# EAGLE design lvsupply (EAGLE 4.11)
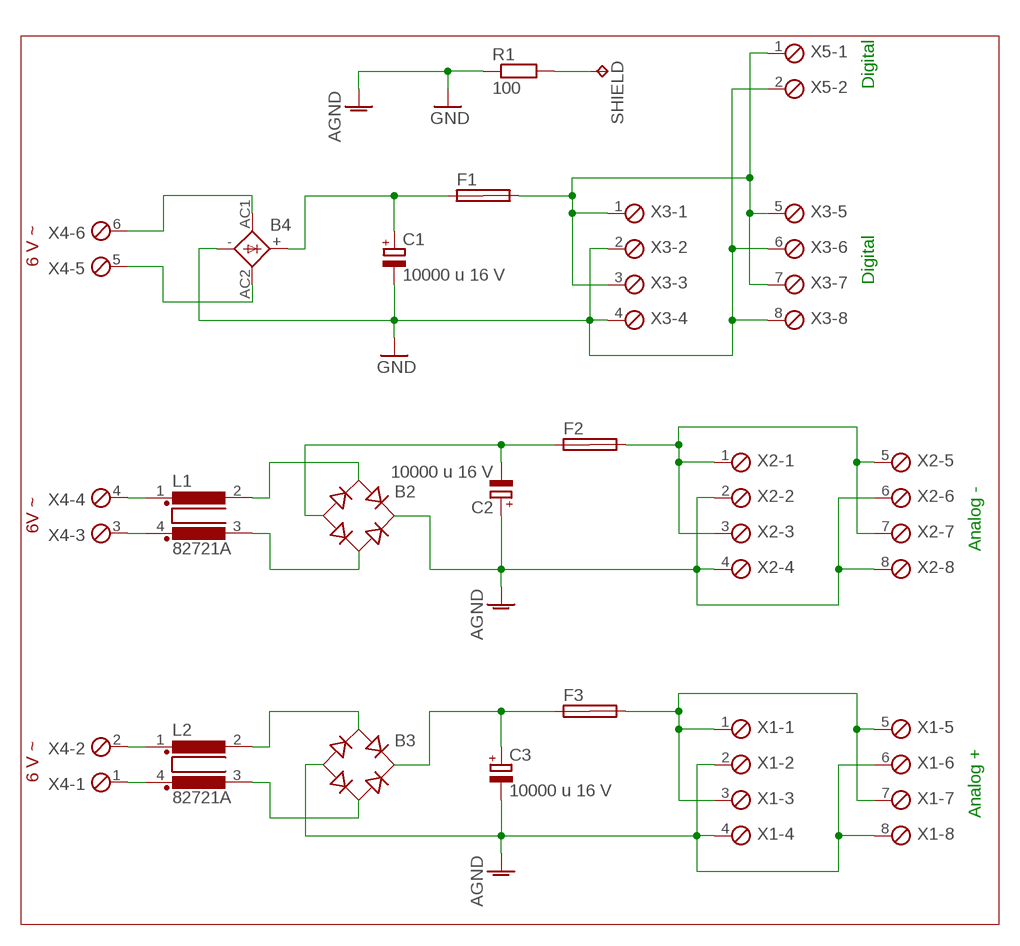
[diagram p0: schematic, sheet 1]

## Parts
B2  RB1A  [RB1A]
B3  RB1A  [RB1A]
B4  SKBB  [SKBB]
C1  10000 u 16 V  CPOL-EUE10-25  [EB25D]
C2  10000 u 16 V  CPOL-EUE10-25  [EB25D]
C3  10000 u 16 V  CPOL-EUE10-25  [EB25D]
F1  SHK20Q  [SHK20Q]
F2  SHK20Q  [SHK20Q]
F3  SHK20Q  [SHK20Q]
L1  82721A  [82721A]
L2  82721A  [82721A]
R1  100  R-EU_0309/12  [0309/12]
SHIELD  TPPAD1-20Y  [P1-20Y]
X1  MPT8  [8POL254]
X2  MPT8  [8POL254]
X3  MPT8  [8POL254]
X4  MPT6  [6POL254]
X5  MPT2  [2POL254]

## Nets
GND: B2.+ B3.- B4.- C1.- C2.+ C3.- R1.1 X1.2 X1.4 X1.6 X1.8 X2.2 X2.4 X2.6 X2.8 X3.2 X3.4 X3.6 X3.8 X5.2 ; supply symbol labelled AGND
N$5: B3.AC2 L2.3
N$6: L2.1 X4.2
N$7: L1.1 X4.4
N$8: B2.AC2 L1.3
N$9: B4.AC1 X4.6
N$10: B4.AC2 X4.5
N$11: B4.+ C1.+ F1.1A
N$12: F1.2A X3.1 X3.3 X3.5 X3.7 X5.1
N$13: B2.- C2.- F2.1A
N$14: B2.AC1 L1.2
N$15: B3.+ C3.+ F3.1A
N$16: F2.2A X2.1 X2.3 X2.5 X2.7
N$17: F3.2A X1.1 X1.3 X1.5 X1.7
N$18: L1.4 X4.3
N$19: L2.4 X4.1
N$20 [Shieldc]: R1.2 SHIELD.1(TP)
N$21: B3.AC1 L2.2
Unconnected: F1.1B F1.2B F2.1B F2.2B F3.1B F3.2B

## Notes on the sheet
- Digital
- 6 V ~
- Digital
- 6V ~
- Analog -
- 6 V ~
- Analog +

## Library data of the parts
B2 B3 = rectifier:RB1A: RECTIFIER 1 A
B4 = rectifier:SKBB: SEMIKRON RECTIFIER
C1-C3 = rcl:CPOL-EU: POLARIZED CAPACITOR, European symbol
F1-F3 = fuse:SHK20Q: FUSE HOLDER 5 x 20 mm, SH contact, E1207 Buerklin 64G6061
L1 L2 = inductors:82721A: FILTER
R1 = rcl:R-EU_: RESISTOR, European symbol
SHIELD = testpad:TP
X1-X3 = con-phoenix-254:MPT8: PHOENIX CONNECTOR
X4 = con-phoenix-254:MPT6: PHOENIX CONNECTOR
X5 = con-phoenix-254:MPT2: PHOENIX CONNECTOR

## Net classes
0 default: width 0.914 mm, drill 0.508 mm
1 Shieldc: drill 2.032 mm

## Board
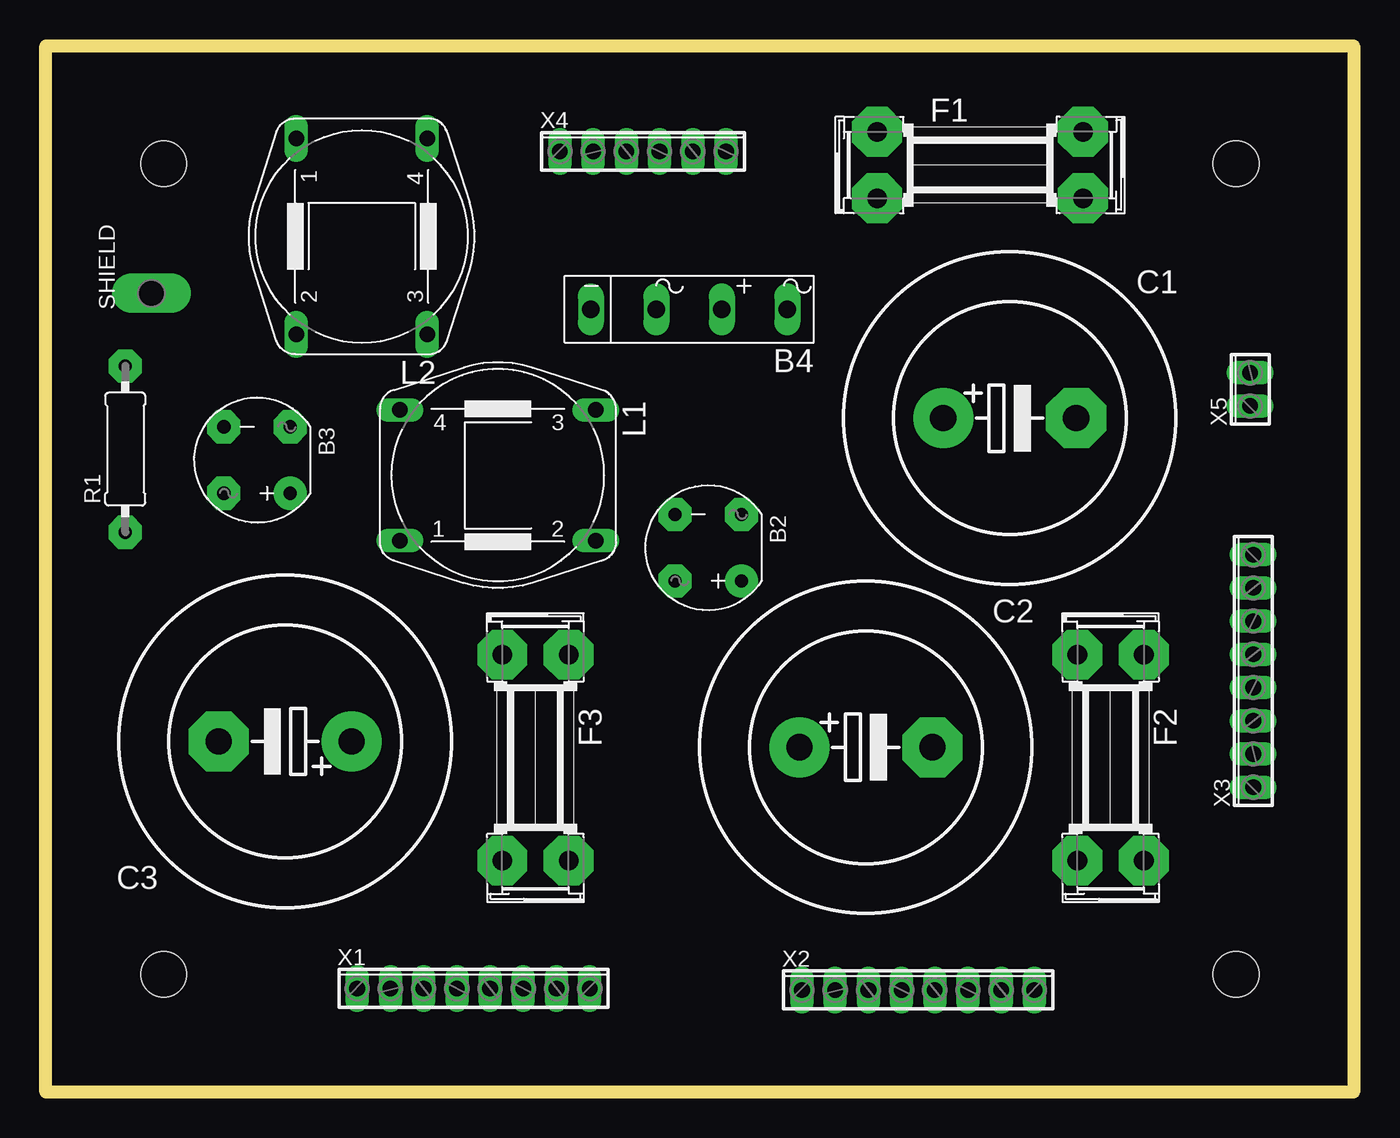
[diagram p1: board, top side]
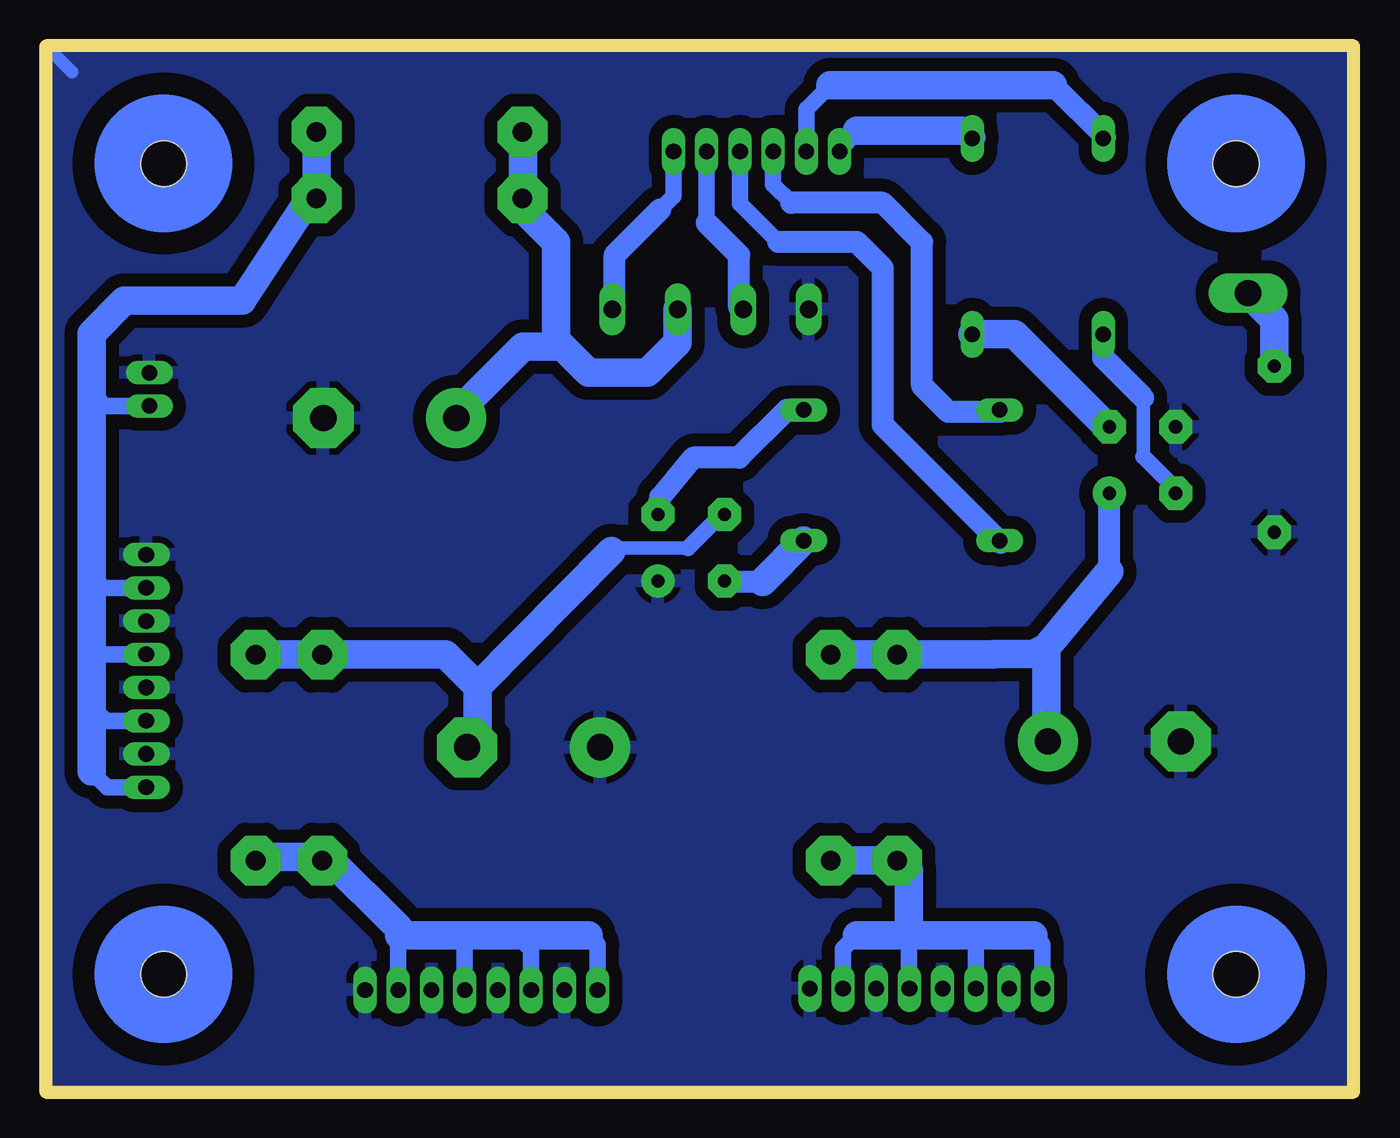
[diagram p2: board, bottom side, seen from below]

Size 100 x 80 mm. Coordinates in mm from the lower left corner, seen from the top.
Outline: 0,0 0,80 100,80 100,0 0,0
Copper layers 16: Bottom 0.035mm
Design rules "default": minimum track width 36mil, minimum drill 24mil, track to track 20mil, track to pad 20mil, pad to pad 20mil, via to via 20mil, smd to smd 20mil, copper to edge 0mil, drill to drill 40mil, minimum pad ring 10mil, minimum via ring 8mil, stop-mask expansion 8mil, vias tented up to drill 0mil, thermal gap 20mil
Holes 3.5 mm at 91,9 9,9 9,71 91,71
bRestrict: area 5,67 to 13,75; area 5,5 to 13,13; area 87,67 to 95,75; area 87,5 to 95,13

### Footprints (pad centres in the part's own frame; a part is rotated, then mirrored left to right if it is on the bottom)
RB1A = drill 1.016 pad 2.54 round: + -2.54,2.54 | drill 1.016 pad 2.54 octagon: - 2.54,-2.54; AC1 2.54,2.54; AC2 -2.54,-2.54
SKBB = drill 1.321 long: + -2.616,0; - 7.391,0; AC1 -7.62,0; AC2 2.388,0
EB25D = drill 2.007 pad 4.597 round: + -5.08,0 | drill 2.007 pad 4.597 octagon: - 5.08,0
SHK20Q = drill 1.5 pad 3.81 octagon: 1A -7.874,2.54; 1B -7.874,-2.54; 2A 7.874,2.54; 2B 7.874,-2.54
82721A = drill 1.194 long: 1 7.493,5.004; 2 -7.493,5.004; 3 -7.493,-5.004; 4 7.493,-5.004
0309/12 = drill 1.016 pad 2.54 octagon: 1 -6.35,0; 2 6.35,0
P1-20Y = drill 2.007 pad 2.54 long: 1 0,0
8POL254 = drill 1.2 long: 1 -8.89,0; 2 -6.35,0; 3 -3.81,0; 4 -1.27,0; 5 1.27,0; 6 3.81,0; 7 6.35,0; 8 8.89,0
6POL254 = drill 1.2 pad 1.778 long: 1 -6.35,0; 2 -3.81,0; 3 -1.27,0; 4 1.27,0; 5 3.81,0; 6 6.35,0
2POL254 = drill 1.2 long: 1 -1.27,0; 2 1.27,0

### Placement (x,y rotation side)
B2  50.65,41.62 180 top
B3  16.15,48.32 180 top
B4  49.07,59.85 180 top
C1  73.7,51.53 0 top
C2  62.7,26.36 0 top
C3  18.3,26.81 180 top
F1  71.43,70.88 0 top
F2  81.41,25.57 270 top
F3  37.44,25.57 270 top
L1  34.57,47.16 180 top
L2  24.16,65.43 90 top
R1  6.08,49.16 90 top
SHIELD  8.08,61.08 90 top
X1  32.7,7.92 0 top
X2  66.7,7.8 0 top
X3  92.32,32.2 90 top
X4  45.66,71.92 0 top
X5  92.08,53.73 90 top

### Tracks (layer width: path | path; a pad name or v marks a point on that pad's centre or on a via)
GND
  Bottom 1: 100,80 0,80 0,0 100,0 100,80 | 100,80 98,78
  Bottom 1.676: B4.- 41.68,58.82 | 79,51.5 78.97,51.53 C1.-
  pour Bottom (isolate 1): 0,80 100,80 100,0 0,0
N$5
  Bottom 1.676: 18.5,50.5 18.69,50.69 B3.AC2
  Bottom 2.184: L2.3 25.94,57.94 18.69,50.69
N$6
  Bottom 1.27: X4.2 41.85,75.15 40,77
  Bottom 1.676: L2.1 19.08,72.92 19,73 23,77
  Bottom 2.184: 23,77 40,77
N$7
  Bottom 1.27: X4.4 46.93,67.93 44,65
  Bottom 1.676: 44,65 38,65 36,63 36,51 27.08,42.08 | 27.08,42.08 27,42 | L1.1 27.08,42.08
N$8
  Bottom 1.676: L1.3 43.34,52.16 47,48.5 50.5,48.5 53,45.5 53.5,44 53.53,44 B2.AC2
N$9
  Bottom 1.27: X4.6 52.01,68.49 53,67.5 | 56.5,60 56.65,59.85 B4.AC1
  Bottom 1.676: 53,67.5 56.5,64 56.5,60
N$10
  Bottom 1.27: 49.47,66.47 X4.5 | 47,60 46.85,59.85 B4.AC2
  Bottom 1.676: 49.47,66.47 47,64 47,60
N$11
  Bottom 1.27: 60.75,57.25 61,57.5 | F1.1A 63.56,73.94 63.5,73 63.5,73.5
  Bottom 1.676: 68.62,51.88 C1.+ | 60.75,57.25 61,57
  Bottom 2.184: B4.+ 51.69,57.31 54,55 58.5,55 60.75,57.25 | 61,57.5 61,65 63.5,67.5 63.5,73 | 68.62,51.88 63.5,57 61,57
N$12
  Bottom 1.27: X3.1 95.31,23.31 96.5,24.5 | X3.3 95.39,28.39 96.5,29.5 | X3.5 95.97,33.47 96.5,34 | X3.7 95.55,38.55 96.5,39.5 | X5.1 95.46,52.46 96.5,53.5
  Bottom 2.184: F1.2A 79.3,69.2 85,60.5 94,60.5 96.5,58 96.5,53.5 96.5,39.5 96.5,34 96.5,29.5 96.5,24.5
N$13
  Bottom 1.016: 50.9,41.6 56.5,41.6 56.75,41.35
  Bottom 1.27: B2.- 48.34,44.16 50.9,41.6
  Bottom 1.676: 67.78,26.22 68,26 | 67.78,26.22 C2.- | 67,27 67.78,26.22
  Bottom 2.184: 56.75,41.35 67,31 | 67,31 67,27 | F2.1A 69.44,33.44 67,31
N$14
  Bottom 1.676: B2.AC1 48.53,39 45.22,39
  Bottom 2.184: L1.2 45.22,39
N$15
  Bottom 1.676: 18.69,39.81 B3.+ | 23.5,27 23.38,26.88 C3.+ | 27.5,33.5 27.56,33.44
  Bottom 2.184: 23.5,34 18.69,39.81 | 23.5,27 23.5,34 | 27.56,33.44 F3.1A | 27.5,33.5 24.5,33.5 23.5,34
N$16
  Bottom 1.27: X2.7 73.05,11.95 73,12 | X2.5 67.97,11.47 68.5,12 | X2.3 62.89,10.89 64,12 | X2.1 57.81,11.31 58.5,12
  Bottom 1.676: 73,12 73,12.5 | 83.95,17.55 84,17.5 | 83.95,17.55 F2.2A | 83.5,18 83.95,17.55
  Bottom 2.184: 73,12.5 78.5,18 83.5,18 | 73,12 68.5,12 64,12 58.5,12
N$17
  Bottom 1.27: X1.5 34,7.95 34,12 | X1.7 39.05,10.95 38,12 | X1.3 28.89,11.39 29.5,12 | X1.1 23.81,11.31 24.5,12
  Bottom 1.676: 34,17 34.7,17.7
  Bottom 2.184: 34.7,17.7 F3.2A | 34,12 34,17 | 34,12 38,12 | 34,12 29.5,12 24.5,12
N$18
  Bottom 1.27: X4.3 44.39,69.39 43,68
  Bottom 1.676: 43,68 36,68 33,65 33,54 31,52 27,52 27,52.09 L1.4
N$19
  Bottom 1.27: X4.1 39.23,72 38,73.5
  Bottom 1.676: 29.08,72.92 29,73 | L2.4 29.08,72.92 | 29.08,72.92 30,73.5
  Bottom 2.184: 30,73.5 38,73.5
N$20
  Bottom 2.184: R1.2 6.08,59.08 SHIELD.1
N$21
  Bottom 1.016: 16.1,48.6 16.1,53.1
  Bottom 1.27: B3.AC1 13.61,45.89 13.5,46 16.1,48.6
  Bottom 1.676: L2.2 19.16,56.16 16.1,53.1
(copper drawn outside any net)
  shapes: Bottom circle x4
